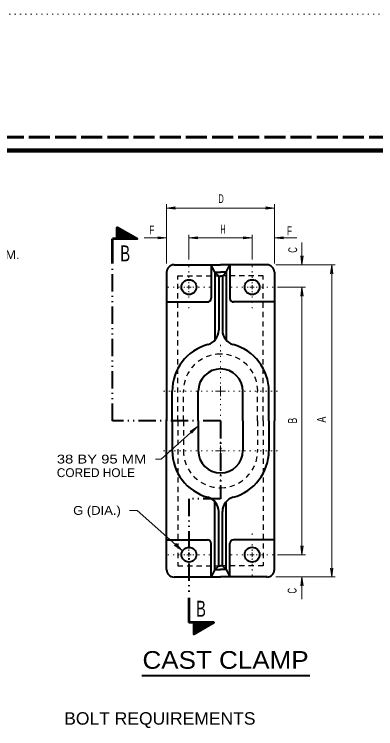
# Model space of a CAD drawing. Extents: x 312583 to 312854, y 144419 to 144597.
# Drawn here: x 312664.2 to 312695.3, y 144535.4 to 144596.8 of the extents above; entities that cross this region are included whole.
import ezdxf
from ezdxf.enums import TextEntityAlignment as Align

# ---------------------------------------------------------------- set-up
doc = ezdxf.new("R2010")
doc.units = 0
doc.header["$LTSCALE"] = 0.3
for name, pattern in [('DASH_DOUBLE_DOT', [9.2, 5, -1.2, 0.3, -1.2, 0.3, -1.2]), ('DOTTED', [1.5, 0.3, -1.2]), ('LONG_DASHED', [7.5, 6, -1.5]), ('SHORT_DASHED', [2.7, 1.5, -1.2])]:
    doc.linetypes.add(name, pattern=pattern)
for name, color, linetype, lineweight in [('1', 7, 'Continuous', 40), ('62', 7, 'DOTTED', 13), ('63', 7, 'LONG_DASHED', 60)]:
    doc.layers.add(name, color=color, linetype=linetype, lineweight=lineweight)

msp = doc.modelspace()

# ---------------------------------------------------------------- linework, layer by layer
at = {"layer": '1', "lineweight": 13}
for p, q in [((312677.2895, 144575.3741), (312677.2895, 144580.4495)), ((312686.5585, 144575.3741), (312686.5585, 144580.4495)), ((312677.2895, 144580.1275), (312678.0638, 144580.2271)), ((312677.2895, 144580.1275), (312686.5585, 144580.1275)), ((312677.2895, 144580.1275), (312678.0638, 144580.0355)), ((312678.0638, 144580.2271), (312677.8185, 144580.1275)), ((312678.0638, 144580.0355), (312677.8185, 144580.1275)), ((312685.7918, 144580.2271), (312686.0372, 144580.1275)), ((312686.5585, 144580.1275), (312685.7918, 144580.2271)), ((312685.7918, 144580.0355), (312686.0372, 144580.1275)), ((312686.5585, 144580.1275), (312685.7918, 144580.0355)), ((312677.2895, 144577.5745), (312675.3728, 144577.5745)), ((312676.5228, 144577.6665), (312676.7682, 144577.5745)), ((312677.2895, 144577.5745), (312676.5228, 144577.6665)), ((312676.5228, 144577.4825), (312676.7682, 144577.5745)), ((312677.2895, 144577.5745), (312676.5228, 144577.4825)), ((312679.2062, 144575.7115), (312679.2062, 144577.8275)), ((312679.2062, 144577.5745), (312679.9805, 144577.6665)), ((312684.6418, 144577.5745), (312679.2062, 144577.5745)), ((312679.2062, 144577.5745), (312679.9805, 144577.4825)), ((312679.9805, 144577.6665), (312679.7352, 144577.5745)), ((312679.9805, 144577.4825), (312679.7352, 144577.5745)), ((312683.8752, 144577.6665), (312684.1205, 144577.5745)), ((312684.6418, 144577.5745), (312683.8752, 144577.6665)), ((312683.8752, 144577.4825), (312684.1205, 144577.5745)), ((312684.6418, 144577.5745), (312683.8752, 144577.4825)), ((312684.6418, 144575.7115), (312684.6418, 144577.8275)), ((312686.5585, 144577.5745), (312687.3252, 144577.6665)), ((312686.5585, 144577.5745), (312688.4752, 144577.5745)), ((312686.5585, 144577.5745), (312687.3252, 144577.4825)), ((312687.3252, 144577.6665), (312687.0798, 144577.5745)), ((312687.3252, 144577.4825), (312687.0798, 144577.5745)), ((312688.9198, 144575.2515), (312688.9198, 144577.1681)), ((312688.8278, 144576.0181), (312688.9198, 144575.7728)), ((312688.9198, 144575.2515), (312688.8278, 144576.0181)), ((312689.0195, 144576.0181), (312688.9198, 144575.7728)), ((312688.9198, 144575.2515), (312689.0195, 144576.0181)), ((312691.7948, 144575.2515), (312686.6888, 144575.2515)), ((312691.4805, 144575.2515), (312691.3808, 144574.4771)), ((312691.4805, 144561.8348), (312691.4805, 144575.2515)), ((312691.4805, 144575.2515), (312691.5725, 144574.4771)), ((312691.3808, 144574.4771), (312691.4805, 144574.7225)), ((312691.5725, 144574.4771), (312691.4805, 144574.7225)), ((312679.2062, 144573.3348), (312679.0298, 144573.3348)), ((312679.2062, 144573.3348), (312679.2062, 144573.5111)), ((312679.2062, 144573.3348), (312679.3902, 144573.3348)), ((312679.2062, 144573.3348), (312679.2062, 144573.1508)), ((312684.6418, 144573.3348), (312684.4578, 144573.3348)), ((312684.6418, 144573.3348), (312684.6418, 144573.5111)), ((312684.6418, 144573.3348), (312684.6418, 144573.1508)), ((312684.6418, 144573.3348), (312684.8258, 144573.3348)), ((312689.2418, 144573.3348), (312686.8268, 144573.3348)), ((312688.9198, 144573.3348), (312688.8278, 144572.5605)), ((312688.9198, 144561.8348), (312688.9198, 144573.3348)), ((312688.9198, 144573.3348), (312689.0195, 144572.5605)), ((312688.8278, 144572.5605), (312688.9198, 144572.8058)), ((312689.0195, 144572.5605), (312688.9198, 144572.8058)), ((312681.9278, 144564.3878), (312681.4908, 144564.3878)), ((312681.9278, 144564.3878), (312681.9278, 144564.8248)), ((312681.9278, 144564.3878), (312682.3648, 144564.3878)), ((312681.9278, 144564.3878), (312681.9278, 144563.9508)), ((312679.9498, 144561.3518), (312676.8072, 144558.5423)), ((312679.9498, 144561.3518), (312679.3058, 144560.9148)), ((312679.9498, 144561.3518), (312679.4362, 144560.7691)), ((312688.9198, 144561.8348), (312688.9198, 144550.3348)), ((312691.4805, 144561.8348), (312691.4805, 144548.4181)), ((312679.3058, 144560.9148), (312679.5588, 144561.0068)), ((312679.4362, 144560.7691), (312679.5588, 144561.0068)), ((312681.9278, 144559.2741), (312681.9278, 144559.7111)), ((312681.9278, 144559.2741), (312681.4908, 144559.2741)), ((312681.9278, 144559.2741), (312682.3648, 144559.2741)), ((312681.9278, 144559.2741), (312681.9278, 144558.8371)), ((312676.8072, 144558.5423), (312676.3449, 144558.5423)), ((312677.9412, 144551.1628), (312678.1942, 144551.0708)), ((312678.5852, 144550.7181), (312677.9412, 144551.1628)), ((312678.0715, 144551.3085), (312678.1942, 144551.0708)), ((312678.5852, 144550.7181), (312678.0715, 144551.3085)), ((312688.8278, 144551.1015), (312688.9198, 144550.8561)), ((312688.9198, 144550.3348), (312688.8278, 144551.1015)), ((312689.0195, 144551.1015), (312688.9198, 144550.8561)), ((312688.9198, 144550.3348), (312689.0195, 144551.1015)), ((312679.2062, 144550.3348), (312679.0298, 144550.3348)), ((312679.2062, 144550.3348), (312679.2062, 144550.5111)), ((312679.2062, 144550.3348), (312679.3902, 144550.3348)), ((312679.2062, 144550.3348), (312679.2062, 144550.1508)), ((312684.6418, 144550.3348), (312684.4578, 144550.3348)), ((312684.6418, 144550.3348), (312684.6418, 144550.5111)), ((312684.6418, 144550.3348), (312684.8258, 144550.3348)), ((312684.6418, 144550.3348), (312684.6418, 144550.1508)), ((312689.2418, 144550.3348), (312686.8268, 144550.3348)), ((312691.3808, 144549.1848), (312691.4805, 144548.9395)), ((312691.4805, 144548.4181), (312691.3808, 144549.1848)), ((312691.5725, 144549.1848), (312691.4805, 144548.9395)), ((312691.4805, 144548.4181), (312691.5725, 144549.1848)), ((312691.7948, 144548.4181), (312686.6888, 144548.4181)), ((312688.9198, 144548.4181), (312688.8278, 144547.6438)), ((312688.9198, 144548.4181), (312688.9198, 144546.5015)), ((312688.9198, 144548.4181), (312689.0195, 144547.6438)), ((312688.8278, 144547.6438), (312688.9198, 144547.8891)), ((312689.0195, 144547.6438), (312688.9198, 144547.8891))]:
    msp.add_line(p, q, dxfattribs=at)
at = {"layer": '1', "lineweight": 35}
for p, q in [((312673.0498, 144578.4331), (312673.0652, 144578.4485)), ((312673.0498, 144578.3948), (312673.0882, 144578.4408)), ((312673.0498, 144578.3488), (312673.0958, 144578.4255)), ((312673.0498, 144578.3028), (312673.1188, 144578.4178)), ((312673.0498, 144578.2568), (312673.1418, 144578.4101)), ((312673.0498, 144578.2261), (312673.1495, 144578.3948)), ((312673.0498, 144578.1801), (312673.1725, 144578.3871)), ((312673.0498, 144578.1341), (312673.1955, 144578.3718)), ((312673.0498, 144578.0958), (312673.2108, 144578.3641)), ((312673.0498, 144578.0575), (312673.2338, 144578.3565)), ((312673.0498, 144578.0038), (312673.2492, 144578.3488)), ((312673.0498, 144577.9655), (312673.2722, 144578.3335)), ((312673.0498, 144577.9271), (312673.2875, 144578.3258)), ((312673.0498, 144577.8735), (312673.3028, 144578.3105)), ((312673.0498, 144577.8351), (312673.3258, 144578.3028)), ((312673.0498, 144577.7968), (312673.3335, 144578.2951)), ((312673.0498, 144577.7508), (312673.3565, 144578.2798)), ((312673.0498, 144577.7048), (312673.3795, 144578.2721)), ((312673.0498, 144577.6665), (312673.3948, 144578.2568)), ((312673.0498, 144577.6281), (312673.4102, 144578.2415)), ((312673.0498, 144577.5745), (312673.4332, 144578.2415)), ((312673.0498, 144577.5438), (312673.4485, 144578.2261)), ((312673.0498, 144577.4978), (312673.4715, 144578.2185)), ((312673.0652, 144577.4748), (312673.4868, 144578.2031)), ((312673.0882, 144577.4748), (312673.5098, 144578.1955)), ((312673.1188, 144577.4748), (312673.5252, 144578.1801)), ((312673.1418, 144577.4748), (312673.5405, 144578.1801)), ((312673.1648, 144577.4748), (312673.5635, 144578.1648)), ((312673.1878, 144577.4825), (312673.5788, 144578.1571)), ((312673.2108, 144577.4825), (312673.5942, 144578.1418)), ((312673.2338, 144577.4748), (312673.6172, 144578.1341)), ((312673.2645, 144577.4748), (312673.6402, 144578.1188)), ((312673.2875, 144577.4748), (312673.6478, 144578.1111)), ((312673.3105, 144577.4748), (312673.6708, 144578.1035)), ((312673.3335, 144577.4748), (312673.6938, 144578.0881)), ((312673.3642, 144577.4748), (312673.7092, 144578.0728)), ((312673.3872, 144577.4748), (312673.7245, 144578.0651)), ((312673.4102, 144577.4825), (312673.7475, 144578.0575)), ((312673.4408, 144577.4748), (312673.7628, 144578.0498)), ((312673.4562, 144577.4748), (312673.7782, 144578.0345)), ((312673.4792, 144577.4748), (312673.8012, 144578.0268)), ((312673.5098, 144577.4748), (312673.8242, 144578.0115)), ((312673.5328, 144577.4748), (312673.8318, 144578.0038)), ((312673.5635, 144577.4748), (312673.8548, 144577.9961)), ((312673.5788, 144577.4748), (312673.8778, 144577.9885)), ((312673.6095, 144577.4748), (312673.8855, 144577.9731)), ((312673.6325, 144577.4825), (312673.9162, 144577.9655)), ((312673.6555, 144577.4748), (312673.9315, 144577.9501)), ((312673.6785, 144577.4748), (312673.9468, 144577.9348)), ((312673.7015, 144577.4748), (312673.9698, 144577.9348)), ((312673.7322, 144577.4748), (312673.9852, 144577.9195)), ((312673.7552, 144577.4748), (312674.0082, 144577.9118)), ((312673.7782, 144577.4748), (312674.0235, 144577.8965)), ((312673.8088, 144577.4748), (312674.0388, 144577.8888)), ((312673.8242, 144577.4748), (312674.0618, 144577.8735)), ((312673.8548, 144577.4748), (312674.0772, 144577.8735)), ((312673.8855, 144577.4748), (312674.0925, 144577.8581)), ((312673.9008, 144577.4748), (312674.1155, 144577.8505)), ((312673.9238, 144577.4748), (312674.1308, 144577.8351)), ((312673.9468, 144577.4748), (312674.1538, 144577.8275)), ((312673.9775, 144577.4748), (312674.1692, 144577.8121)), ((312674.0082, 144577.4748), (312674.1922, 144577.8045)), ((312674.0235, 144577.4748), (312674.2075, 144577.7968)), ((312674.0542, 144577.4748), (312674.2228, 144577.7815)), ((312674.0695, 144577.4748), (312674.2458, 144577.7661)), ((312674.1002, 144577.4748), (312674.2612, 144577.7585)), ((312674.1232, 144577.4748), (312674.2765, 144577.7508)), ((312674.1462, 144577.4748), (312674.2995, 144577.7431)), ((312674.1768, 144577.4748), (312674.3148, 144577.7278)), ((312674.1922, 144577.4748), (312674.3302, 144577.7201)), ((312674.2228, 144577.4748), (312674.3608, 144577.7048)), ((312674.2458, 144577.4748), (312674.3762, 144577.6971)), ((312674.2688, 144577.4748), (312674.3915, 144577.6895)), ((312674.2995, 144577.4748), (312674.4145, 144577.6818)), ((312674.3148, 144577.4748), (312674.4298, 144577.6665)), ((312674.3455, 144577.4748), (312674.4452, 144577.6588)), ((312674.3685, 144577.4748), (312674.4682, 144577.6435)), ((312674.3915, 144577.4748), (312674.4835, 144577.6281)), ((312674.4222, 144577.4748), (312674.4988, 144577.6281)), ((312674.4452, 144577.4748), (312674.5218, 144577.6128)), ((312674.4682, 144577.4748), (312674.5372, 144577.5975)), ((312674.4988, 144577.4748), (312674.5602, 144577.5898)), ((312674.5142, 144577.4748), (312674.5755, 144577.5745)), ((312674.5372, 144577.4748), (312674.5985, 144577.5668)), ((312674.5602, 144577.4748), (312674.6138, 144577.5591)), ((312674.5908, 144577.4748), (312674.6292, 144577.5515)), ((312674.6215, 144577.4748), (312674.6522, 144577.5361)), ((312674.6368, 144577.4748), (312674.6675, 144577.5285)), ((312674.6675, 144577.4748), (312674.6828, 144577.5131)), ((312674.6828, 144577.4748), (312674.7058, 144577.5055)), ((312674.7135, 144577.4748), (312674.7212, 144577.4978)), ((312674.7442, 144577.4748), (312674.7442, 144577.4901)), ((312679.6278, 144544.4775), (312680.0572, 144543.7568)), ((312679.6278, 144544.4315), (312680.0265, 144543.7491)), ((312679.6278, 144544.4008), (312680.0112, 144543.7338)), ((312679.6278, 144544.3471), (312679.9958, 144543.7338)), ((312679.6278, 144544.3088), (312679.9728, 144543.7185)), ((312679.6278, 144544.2705), (312679.9575, 144543.7031)), ((312679.6278, 144544.2245), (312679.9345, 144543.6955)), ((312679.6278, 144544.1785), (312679.9192, 144543.6801)), ((312679.6278, 144544.1401), (312679.9038, 144543.6725)), ((312679.6278, 144544.1018), (312679.8808, 144543.6648)), ((312679.6432, 144544.5005), (312680.0648, 144543.7721)), ((312679.6738, 144544.5005), (312680.0878, 144543.7798)), ((312679.6968, 144544.5005), (312680.1108, 144543.7951)), ((312679.7198, 144544.5005), (312680.1185, 144543.7951)), ((312679.7505, 144544.5005), (312680.1415, 144543.8105)), ((312679.7658, 144544.4928), (312680.1645, 144543.8181)), ((312679.7965, 144544.4928), (312680.1798, 144543.8335)), ((312679.8118, 144544.5005), (312680.1952, 144543.8411)), ((312679.8425, 144544.5005), (312680.2182, 144543.8565)), ((312679.8732, 144544.5005), (312680.2335, 144543.8641)), ((312679.8885, 144544.5005), (312680.2488, 144543.8718)), ((312679.9192, 144544.5005), (312680.2718, 144543.8871)), ((312679.9422, 144544.5005), (312680.2948, 144543.9025)), ((312679.9652, 144544.5005), (312680.3025, 144543.9101)), ((312679.9958, 144544.4928), (312680.3255, 144543.9178)), ((312680.0188, 144544.5005), (312680.3485, 144543.9255)), ((312680.0418, 144544.5005), (312680.3638, 144543.9408)), ((312680.0572, 144544.5005), (312680.3792, 144543.9485)), ((312680.0878, 144544.5005), (312680.4022, 144543.9638)), ((312680.1185, 144544.5005), (312680.4175, 144543.9715)), ((312680.1415, 144544.5005), (312680.4328, 144543.9791)), ((312680.1645, 144544.5005), (312680.4558, 144543.9868)), ((312680.1875, 144544.5005), (312680.4712, 144544.0021)), ((312680.2105, 144544.4928), (312680.4942, 144544.0098)), ((312680.2412, 144544.5005), (312680.5095, 144544.0251)), ((312680.2565, 144544.5005), (312680.5325, 144544.0405)), ((312680.2872, 144544.5005), (312680.5478, 144544.0405)), ((312680.3102, 144544.5005), (312680.5632, 144544.0558)), ((312680.3332, 144544.5005), (312680.5862, 144544.0635)), ((312680.3638, 144544.5005), (312680.6092, 144544.0788)), ((312680.3868, 144544.5005), (312680.6168, 144544.0865)), ((312680.4098, 144544.5005), (312680.6398, 144544.1018)), ((312680.4328, 144544.5005), (312680.6628, 144544.1018)), ((312680.4635, 144544.5005), (312680.6705, 144544.1171)), ((312680.4865, 144544.5005), (312680.6935, 144544.1248)), ((312680.5018, 144544.5005), (312680.7165, 144544.1401)), ((312680.5325, 144544.5005), (312680.7318, 144544.1478)), ((312680.5555, 144544.5005), (312680.7472, 144544.1631)), ((312680.5862, 144544.5005), (312680.7702, 144544.1708)), ((312680.6092, 144544.5005), (312680.7932, 144544.1785)), ((312680.6322, 144544.5005), (312680.8008, 144544.1938)), ((312680.6552, 144544.5005), (312680.8238, 144544.2091)), ((312680.6782, 144544.5005), (312680.8468, 144544.2168)), ((312680.7012, 144544.5005), (312680.8545, 144544.2245)), ((312680.7318, 144544.5005), (312680.8775, 144544.2321)), ((312680.7548, 144544.5005), (312680.9005, 144544.2475)), ((312680.7778, 144544.5005), (312680.9158, 144544.2551)), ((312680.8008, 144544.5005), (312680.9388, 144544.2705)), ((312680.8238, 144544.5005), (312680.9542, 144544.2781)), ((312680.8545, 144544.5005), (312680.9772, 144544.2858)), ((312680.8775, 144544.5005), (312680.9925, 144544.2935)), ((312680.9005, 144544.5005), (312681.0078, 144544.3088)), ((312680.9235, 144544.5005), (312681.0308, 144544.3165)), ((312680.9465, 144544.5005), (312681.0462, 144544.3318)), ((312680.9772, 144544.5005), (312681.0615, 144544.3471)), ((312681.0002, 144544.5005), (312681.0845, 144544.3471)), ((312681.0308, 144544.5005), (312681.0998, 144544.3625)), ((312681.0462, 144544.5005), (312681.1152, 144544.3778)), ((312681.0768, 144544.5005), (312681.1382, 144544.3855)), ((312681.0998, 144544.5005), (312681.1612, 144544.4008)), ((312681.1152, 144544.5005), (312681.1765, 144544.4085)), ((312681.1458, 144544.5005), (312681.1918, 144544.4161)), ((312681.1688, 144544.5005), (312681.2148, 144544.4238)), ((312681.1995, 144544.5005), (312681.2302, 144544.4391)), ((312681.2225, 144544.5005), (312681.2455, 144544.4468)), ((312681.2455, 144544.5005), (312681.2685, 144544.4621)), ((312681.2685, 144544.5005), (312681.2838, 144544.4698)), ((312681.2915, 144544.5005), (312681.2992, 144544.4775)), ((312681.3222, 144544.5005), (312681.3222, 144544.4851)), ((312679.6278, 144544.0481), (312679.8732, 144543.6495)), ((312679.6278, 144544.0098), (312679.8502, 144543.6418)), ((312679.6278, 144543.9715), (312679.8272, 144543.6265)), ((312679.6278, 144543.9178), (312679.8118, 144543.6188)), ((312679.6278, 144543.8795), (312679.7888, 144543.6111)), ((312679.6278, 144543.8411), (312679.7735, 144543.6035)), ((312679.6278, 144543.7951), (312679.7505, 144543.5881)), ((312679.6278, 144543.7491), (312679.7352, 144543.5805)), ((312679.6278, 144543.7185), (312679.7198, 144543.5651)), ((312679.6278, 144543.6725), (312679.6968, 144543.5575)), ((312679.6278, 144543.6265), (312679.6815, 144543.5498)), ((312679.6278, 144543.5805), (312679.6662, 144543.5345)), ((312679.6278, 144543.5421), (312679.6432, 144543.5268))]:
    msp.add_line(p, q, dxfattribs=at)
at = {"layer": '1', "lineweight": 53}
for p, q in [((312672.6282, 144575.3511), (312672.6282, 144577.4748)), ((312673.0498, 144577.4748), (312672.6282, 144577.4748)), ((312679.2062, 144546.6241), (312679.2062, 144544.5005)), ((312679.6278, 144544.5005), (312679.2062, 144544.5005))]:
    msp.add_line(p, q, dxfattribs=at)
at = {"layer": '1', "linetype": 'DOTTED', "lineweight": 13}
for p, q in [((312679.2062, 144573.6721), (312679.2062, 144575.4201)), ((312684.6418, 144573.6721), (312684.6418, 144575.4201)), ((312678.8688, 144573.3348), (312677.1208, 144573.3348)), ((312679.2062, 144572.9975), (312679.2062, 144571.2418)), ((312679.5435, 144573.3348), (312681.2992, 144573.3348)), ((312684.3045, 144573.3348), (312682.5565, 144573.3348)), ((312684.6418, 144572.9975), (312684.6418, 144571.2418)), ((312684.9792, 144573.3348), (312686.7272, 144573.3348)), ((312681.9278, 144565.0395), (312681.9278, 144568.5891)), ((312681.2685, 144564.3878), (312676.9368, 144564.3878)), ((312682.5795, 144564.3878), (312686.9878, 144564.3878)), ((312681.9278, 144563.7361), (312681.9278, 144561.8348)), ((312681.9278, 144559.9335), (312681.9278, 144561.8348)), ((312681.2685, 144559.2741), (312676.9368, 144559.2741)), ((312682.5795, 144559.2741), (312686.9878, 144559.2741)), ((312681.9278, 144558.6225), (312681.9278, 144555.0728)), ((312679.2062, 144550.6721), (312679.2062, 144552.4201)), ((312684.6418, 144550.6721), (312684.6418, 144552.4201)), ((312678.8688, 144550.3348), (312677.1208, 144550.3348)), ((312679.5435, 144550.3348), (312681.2992, 144550.3348)), ((312684.3045, 144550.3348), (312682.5565, 144550.3348)), ((312684.9792, 144550.3348), (312686.7272, 144550.3348)), ((312679.2062, 144549.9975), (312679.2062, 144548.2418)), ((312684.6418, 144549.9975), (312684.6418, 144548.2418))]:
    msp.add_line(p, q, dxfattribs=at)
at = {"layer": '1'}
for p, q in [((312677.9335, 144575.2515), (312681.9278, 144575.2515)), ((312681.1228, 144575.2515), (312681.1228, 144572.3765)), ((312681.4448, 144574.6075), (312681.1228, 144575.2515)), ((312685.9222, 144575.2515), (312681.9278, 144575.2515)), ((312682.4032, 144574.6075), (312682.7252, 144575.2515)), ((312682.7252, 144575.2515), (312682.7252, 144572.3765)), ((312677.2895, 144574.6075), (312677.2895, 144561.8348)), ((312681.4448, 144574.6075), (312681.9278, 144574.6075)), ((312681.4448, 144574.6075), (312681.4448, 144568.7731)), ((312681.7668, 144574.2855), (312681.7668, 144569.6241)), ((312682.4032, 144574.6075), (312681.9278, 144574.6075)), ((312682.0812, 144574.2855), (312682.0812, 144569.6241)), ((312682.4032, 144574.6075), (312682.4032, 144568.7731)), ((312686.5585, 144574.6075), (312686.5585, 144561.8348)), ((312677.2895, 144572.0545), (312680.8085, 144572.0545)), ((312686.5585, 144572.0545), (312683.0472, 144572.0545)), ((312677.7725, 144561.8348), (312677.7725, 144564.3878)), ((312680.0112, 144561.8348), (312680.0112, 144564.3878)), ((312683.8445, 144561.8348), (312683.8445, 144564.3878)), ((312686.0755, 144561.8348), (312686.0755, 144564.3878)), ((312677.2895, 144549.0545), (312677.2895, 144561.8348)), ((312677.7725, 144561.8348), (312677.7725, 144559.2741)), ((312680.0112, 144561.8348), (312680.0112, 144559.2741)), ((312683.8445, 144561.8348), (312683.8445, 144559.2741)), ((312686.0755, 144561.8348), (312686.0755, 144559.2741)), ((312686.5585, 144549.0545), (312686.5585, 144561.8348)), ((312681.4448, 144549.0545), (312681.4448, 144554.8888)), ((312682.4032, 144549.0545), (312682.4032, 144554.8888)), ((312681.7668, 144549.3765), (312681.7668, 144554.0378)), ((312682.0812, 144549.3765), (312682.0812, 144554.0378)), ((312677.2895, 144551.6075), (312680.8085, 144551.6075)), ((312686.5585, 144551.6075), (312683.0472, 144551.6075)), ((312681.1228, 144548.4181), (312681.1228, 144551.2931)), ((312682.7252, 144548.4181), (312682.7252, 144551.2931)), ((312681.4448, 144549.0545), (312681.1228, 144548.4181)), ((312681.4448, 144549.0545), (312681.9278, 144549.0545)), ((312682.4032, 144549.0545), (312681.9278, 144549.0545)), ((312682.4032, 144549.0545), (312682.7252, 144548.4181)), ((312677.9335, 144548.4181), (312681.9278, 144548.4181)), ((312685.9222, 144548.4181), (312681.9278, 144548.4181)), ((312675.1495, 144539.9618), (312689.6071, 144539.9618))]:
    msp.add_line(p, q, dxfattribs=at)
at = {"layer": '1', "linetype": 'SHORT_DASHED', "lineweight": 25}
for p, q in [((312678.7308, 144561.8348), (312678.7308, 144564.3878)), ((312685.1172, 144561.8348), (312685.1172, 144564.3878)), ((312678.7308, 144561.8348), (312678.7308, 144559.2741)), ((312685.1172, 144561.8348), (312685.1172, 144559.2741))]:
    msp.add_line(p, q, dxfattribs=at)
at = {"layer": '1', "lineweight": 158}
msp.add_lwpolyline([(312616.5, 144423.1446), (312616.5, 144585.0846), (312849, 144585.0846)], dxfattribs=at)
at = {"layer": '1', "lineweight": 53}
for points in [[(312673.0498, 144577.4748), (312673.0498, 144578.4638), (312674.7518, 144577.4748)], [(312679.6278, 144544.5005), (312679.6278, 144543.5115), (312681.3375, 144544.5005)]]:
    msp.add_lwpolyline(points, close=True, dxfattribs=at)
at = {"layer": '1', "linetype": 'DASH_DOUBLE_DOT'}
for points in [[(312681.9278, 144561.8348), (312672.6282, 144561.8348), (312672.6282, 144574.9985)], [(312681.9278, 144561.8348), (312681.9278, 144555.1341), (312679.2062, 144555.1341), (312679.2062, 144547.1071)]]:
    msp.add_lwpolyline(points, dxfattribs=at)
at = {"layer": '1', "linetype": 'SHORT_DASHED', "lineweight": 25}
for points in [[(312678.2478, 144561.8348), (312678.2478, 144574.2931), (312681.9278, 144574.2931)], [(312685.6002, 144561.8348), (312685.6002, 144574.2931), (312681.9278, 144574.2931)], [(312678.2478, 144561.8348), (312678.2478, 144549.3765), (312681.9278, 144549.3765)], [(312685.6002, 144561.8348), (312685.6002, 144549.3765), (312681.9278, 144549.3765)]]:
    msp.add_lwpolyline(points, dxfattribs=at)
at = {"layer": '1'}
for points in [[(312681.4448, 144574.6075), (312681.7668, 144574.2855), (312681.9278, 144574.2855)], [(312682.4032, 144574.6075), (312682.0812, 144574.2855), (312681.9278, 144574.2855)], [(312681.4448, 144549.0545), (312681.7668, 144549.3765), (312681.9278, 144549.3765)], [(312682.4032, 144549.0545), (312682.0812, 144549.3765), (312681.9278, 144549.3765)]]:
    msp.add_lwpolyline(points, dxfattribs=at)
at = {"layer": '1', "lineweight": 13}
msp.add_lwpolyline([(312678.5852, 144550.7181), (312674.7518, 144554.1451), (312674.1078, 144554.1451)], dxfattribs=at)
at = {"layer": '1'}
for centre in [(312679.2087, 144573.3322), (312684.6418, 144573.3322), (312679.2087, 144550.3322), (312684.6418, 144550.3322)]:
    msp.add_circle(centre, 0.6389, dxfattribs=at)
for centre, radius, start, end in [((312677.9309, 144574.61), 0.6389, 90, 180), ((312685.9196, 144574.61), 0.6389, 0, 90), ((312680.8059, 144572.3739), 0.3194, 270, 0), ((312683.0446, 144572.3739), 0.3194, 180, 270), ((312680.4891, 144569.625), 1.2778, 285.3355, 0), ((312683.3615, 144569.625), 1.2778, 180, 254.6645), ((312681.9253, 144564.3878), 4.1528, 105.33548, 180), ((312681.9253, 144564.3878), 4.1528, 0, 74.66452), ((312681.9253, 144564.3878), 1.9167, 90, 180), ((312681.9253, 144564.3878), 1.9167, 0, 90), ((312681.9253, 144559.2767), 4.1528, 180, 254.66452), ((312681.9253, 144559.2767), 1.9167, 180, 270), ((312681.9253, 144559.2767), 1.9167, 270, 0), ((312681.9253, 144559.2767), 4.1528, 285.33548, 0), ((312680.4891, 144554.0395), 1.2778, 0, 74.6645), ((312683.3615, 144554.0395), 1.2778, 105.3355, 180), ((312680.8059, 144551.2906), 0.3194, 0, 90), ((312683.0446, 144551.2906), 0.3194, 90, 180), ((312677.9309, 144549.0545), 0.6389, 180, 270), ((312685.9196, 144549.0545), 0.6389, 270, 0)]:
    msp.add_arc(centre, radius, start, end, dxfattribs=at)
at = {"layer": '1', "linetype": 'SHORT_DASHED', "lineweight": 25}
for centre, start, end in [((312681.9253, 144564.3878), 90, 180), ((312681.9253, 144564.3878), 0, 90), ((312681.9253, 144559.2767), 180, 270), ((312681.9253, 144559.2767), 270, 0)]:
    msp.add_arc(centre, 3.1944, start, end, dxfattribs=at)
at = {"layer": '62'}
msp.add_line((312601.2, 144596.7846), (312853.5, 144596.7846), dxfattribs=at)
at = {"layer": '63'}
msp.add_line((312851.75, 144586.2246), (312583.526, 144586.2246), dxfattribs=at)

# ---------------------------------------------------------------- texts
at = {"layer": '1'}
for s, width, p in [('D', 0.65, (312681.7262, 144580.554)), ('F', 0.7, (312675.7939, 144577.8649)), ('H', 0.6, (312681.9095, 144577.9301)), ('F', 0.7, (312687.6389, 144577.794)), ('STIFFENERS ALUM.', 1.1, (312653.9726, 144575.7443)), ('38 BY 95 MM', 1.25, (312667.85, 144558.1698)), ('G (DIA.)', 1.1, (312669.2525, 144553.7589))]:
    msp.add_text(s, height=0.76, dxfattribs=dict(at, width=width)).set_placement(p)
for s, height, width, p in [('B', 1.365, 0.7, (312673.7283, 144575.5505)), ('B', 1.365, 0.7, (312680.245, 144545.0065)), ('CAST CLAMP', 1.52, 1.1, (312682.3568, 144540.5262)), ('BOLT REQUIREMENTS', 1.07, 1.05, (312676.7073, 144535.7226))]:
    msp.add_text(s, height=height, dxfattribs=dict(at, width=width)).set_placement(p, align=Align.CENTER)
for s, width, p in [('C', 0.65, (312688.5094, 144576.2907)), ('B', 0.7, (312688.4939, 144561.6234)), ('A', 0.75, (312690.9838, 144561.6919)), ('C', 0.65, (312688.4585, 144546.9945))]:
    msp.add_text(s, height=0.76, rotation=90, dxfattribs=dict(at, width=width)).set_placement(p)
msp.add_text('CORED HOLE', height=0.76, dxfattribs=at).set_placement((312667.85, 144557.0035))

doc.saveas('drawing.dxf')
